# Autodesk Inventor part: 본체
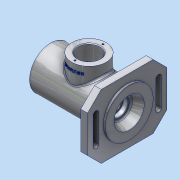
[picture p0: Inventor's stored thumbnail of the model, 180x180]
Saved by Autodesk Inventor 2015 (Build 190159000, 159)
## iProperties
Created: 2017-10
Part Number: 본체
Material: 알루미늄 6061
Document SubType Name: Modeling
Designer: SCD-A13
Density: 2.7 g/cm^3
Appearance: 알루미늄 - 평지
Mass: 730.425 g
Surface Area: 657.614 cm^2
Volume: 270.528 cm^3
Author: SCD-A13
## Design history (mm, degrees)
sketch "스케치1"
  geometry: L1 (-57.5, 0)-(57.5, 0); L2 (-57.5, 31)-(57.5, 31); L3 (57.5, 31)-(57.5, 0); L4 (57.5, 0)-(-57.5, 0); L5 (-57.5, 0)-(-57.5, 31); 2 further points
  constraints: 10 end point, 2 horizontal, 2 midpoint, 2 parallel, 1 coincident, 1 perpendicular
  dimensions: "d0" = 115 distance of L1.start L1.end; "d1" = 62 diameter of L2 L1; "d2" = 115 distance between parallel lines of L3 L5
revolve "회전1" sketch "스케치1" stored, may be unused: angle "d3" = 90 deg
node "작업 평면1"
sketch "스케치3"
  geometry: L1 (-38, -47)-(38, -47); L2 (58, -27)-(58, 27); L3 (38, 47)-(-38, 47); L4 (-58, 27)-(-58, -27); L5 (-58, -47)-(58, 47); L6 (58, -47)-(-58, 47); L7 (-38, 47)-(-58, 27); L8 (-58, -27)-(-38, -47); L9 (38, -47)-(58, -27); L10 (58, 27)-(38, 47); C1 r 31 at (0, 0) reference; 1 further point
  constraints: 20 end point, 8 point on line, 2 midpoint, 2 parallel, 1 horizontal, 1 perpendicular
  dimensions: "d15" = 116 distance of L6.end L5.end; "d16" = 94 distance of L5.end L6.start; "d17" = 20 distance of L3.end L6.end; "d18" = 20 distance of L4.start L6.end (= d17); "d19" = 20 distance of L4.end L5.start (= d17); "d20" = 20 distance of L1.start L5.start (= d19); "d21" = 20 distance of L1.end L6.start (= d17); "d22" = 20 distance of L2.start L6.start (= d21); "d23" = 20 distance of L2.end L5.end (= d17); "d24" = 20 distance of L3.start L5.end (= d23)
extrude "돌출1" join sketch "스케치3" distance "d25" = 10; taper "d26" = 0 deg
sketch "스케치4"
  geometry: 1 further point
revolve "회전2" stored, may be unused: angle "d61" = 90 deg
sketch "스케치6"
  geometry: L1 (38, 47)-(-38, 47) reference; L2 (-46, 20)-(-46, -20); L3 (-50, 20)-(-50, -20); L4 (-42, -20)-(-42, 20); L5 (0, 0)-(0, 47); L6 (42, -20)-(42, 20); L7 (50, 20)-(50, -20); C1 r 31 at (0, 0) reference; A1 r 4 centre (-46, 20) between (-42, 20) and (-50, 20); A2 r 4 centre (-46, -20) between (-50, -20) and (-42, -20); A3 r 4 centre (46, 20) between (50, 20) and (42, 20); A4 r 4 centre (46, -20) between (42, -20) and (50, -20); 1 further point
  constraints: 14 end point, 8 point on circle, 6 symmetric about line, 4 centre point, 4 tangent, 2 midpoint, 1 horizontal alignment, 1 parallel, 1 vertical, 2 other
  dimensions: "d62" = 40 distance of L2.start L2.end; "d63" = 8 diameter of A2; "d64" = 92 distance of A4.centre L2.end
extrude "돌출2" cut sketch "스케치6" stored distance "d65" = 10; taper "d66" = 0 deg
sketch "스케치7"
  geometry: L1 (-112, 7)-(-112, 69) reference; C1 r 16 at (-56, 38); C2 r 25 at (-56, 38); 1 further point
  constraints: 2 centre point, 1 coincident
  dimensions: "d67" = 32 diameter of C1; "d68" = 50 diameter of C2; "d69" = 56 distance from line of L1 C1.centre
extrude "돌출3" join sketch "스케치7" stored distance "d70" = 10; taper "d71" = 0 deg
extrude "돌출4" cut sketch "스케치7" stored distance "d72" = 10; taper "d73" = 0 deg
sketch "스케치8" dims "d74" = 41
  geometry: C1 r 25 at (0, 0) reference; 3 further points
  constraints: 1 coincident, 1 vertical alignment, 2 other
hole "구멍1" sketch "스케치8" at (0, 20.5) diameter "d75" = 2.459; stored, may be unused: countersink angle "d79" = 90 deg, drill point angle "d81" = 118 deg; dims "d76" = 6, "d77" = 4, "d78" = 2, "d80" = 8
sketch "스케치9"
  geometry: L1 (-112, -4)-(-112, 58) reference; L2 (-81, 74)-(-31, 74) reference; 2 further points
  constraints: 1 other
  dimensions: "d85" = 56 distance from line of point (-56, 64) L1; "d86" = 10 distance from line of L2 point (-56, 64)
feature "엠보싱1" sketch "스케치9" dims "d20" = 20 (= d19), "d87" = 0.5, "d88" = 0
fillet "모깎기1" dims "d89" = 0.3
chamfer "모따기1" distance "d90" = 0.7; stored, may be unused: second distance "d91" = 2, angle "d92" = 30 deg
fillet "모깎기2" dims "d93" = 3
fillet "모깎기3" dims "d94" = 0.3
sketch "스케치10"
  geometry: C1 r 31 at (0, 0) reference; 1 further point
  constraints: 1 coincident
hole "구멍2" sketch "스케치10" at (0, 0) diameter "d95" = 40.376; stored, may be unused: countersink angle "d99" = 90 deg, drill point angle "d101" = 118 deg; dims "d96" = 9, "d97" = 4, "d98" = 2, "d100" = 12
fillet "모깎기4" dims "d102" = 3
chamfer "모따기2" distance "d103" = 1; stored, may be unused: second distance "d104" = 2, angle "d105" = 45 deg
sketch "스케치11"
  geometry: C1 r 31 at (0, 0) reference; C2 r 35 at (0, 0)
  constraints: 1 centre point, 1 coincident
  dimensions: "d107" = 35 radius of C2
extrude "돌출5" join sketch "스케치11" distance "d108" = 3; taper "d109" = 0 deg
node "솔리드1"
pattern_circular "원형 패턴1" dims angle "d83" = 360 deg
sketch "스케치5"
  geometry: L1 (-48.5, 0)-(-48.5, 24); L2 (-48.5, 24)-(-45.5, 24); L3 (-45.5, 24)-(-45.5, 20); L4 (-45.5, 20)-(-36.5, 20); L5 (-36.5, 20)-(-36.5, 17.5); L6 (-36.5, 17.5)-(-33.25, 17.5); L7 (-33.25, 17.5)-(-33.25, 18.5); L8 (-33.25, 18.5)-(-31.5, 18.5); L9 (-31.5, 18.5)-(-31.5, 17.5); L10 (-31.5, 17.5)-(-20.5, 17.5); L11 (-20.5, 17.5)-(-20.5, 26); L12 (-20.5, 26)-(17.5, 26); L13 (17.5, 26)-(17.5, 17.5); L14 (17.5, 17.5)-(28.5, 17.5); L15 (28.5, 17.5)-(28.5, 16.5); L16 (43.5, 16)-(57.5, 22); L17 (57.5, -31)-(57.5, 31) reference; L18 (-57.5, -31)-(-57.5, 31) reference; L19 (57.5, 0)-(57.5, 22); L20 (-57.5, 0)-(57.5, 0); L21 (28.5, 16.5)-(33.5, 16.5); L22 (33.5, 16.5)-(33.5, 10); L23 (33.5, 10)-(36.2, 10); L24 (36.2, 10)-(36.2, 12.5); L25 (36.2, 12.5)-(43.5, 12.5); L26 (43.5, 12.5)-(43.5, 16); 2 further points
  constraints: 48 end point, 20 perpendicular, 5 point on line, 2 midpoint, 1 collinear, 1 horizontal
  dimensions: "d27" = 14 horizontal distance of L16.start L16.end; "d33" = 3 distance of L1.end L2.end; "d34" = 12 distance from line of L3 point (-57.5, 21); "d36" = 21 distance between parallel lines of L5 L18; "d37" = 26 distance from line of L8.end L18; "d38" = 1.75 distance of L7.end L8.end; "d41" = 38 distance of L11.end L12.end; "d42" = 60 horizontal distance of L14.end L8.end; "d43" = 11 distance of L9.end L10.end; "d45" = 52 diameter of L12 L20; "d46" = 35 diameter of L10 L20; "d47" = 37 diameter of L7.end L20; "d48" = 40 diameter of L4 L20; "d50" = 48 diameter of L2 L20; "d51" = 35 diameter of L14 L20; "d52" = 5 distance of L15.end L21.end; "d53" = 33 diameter of L21 L20; "d54" = 32 diameter of L16.start L20; "d55" = 25 diameter of L25 L20; "d56" = 20 diameter of L23 L20; "d57" = 44 diameter of L16.end L20; "d59" = 2.7 distance of L22.end L23.end; "d60" = 115 distance of L20.start L19.start (derived)
node "절단 모서리 투영1"
other parameters: "d14" = -3
